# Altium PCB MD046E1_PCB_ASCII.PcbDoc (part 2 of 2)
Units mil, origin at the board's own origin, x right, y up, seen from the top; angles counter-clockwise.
Board outline 4143.7 x 2795.28 mil, 4 copper layers (Top Layer, Signal Layer 1, Signal Layer 2, Bottom Layer), stack 62.8 mil thick; 159 components, 76 nets, 432 pads, 579 vias.
Unrouted connection lines stored in the file: 13.
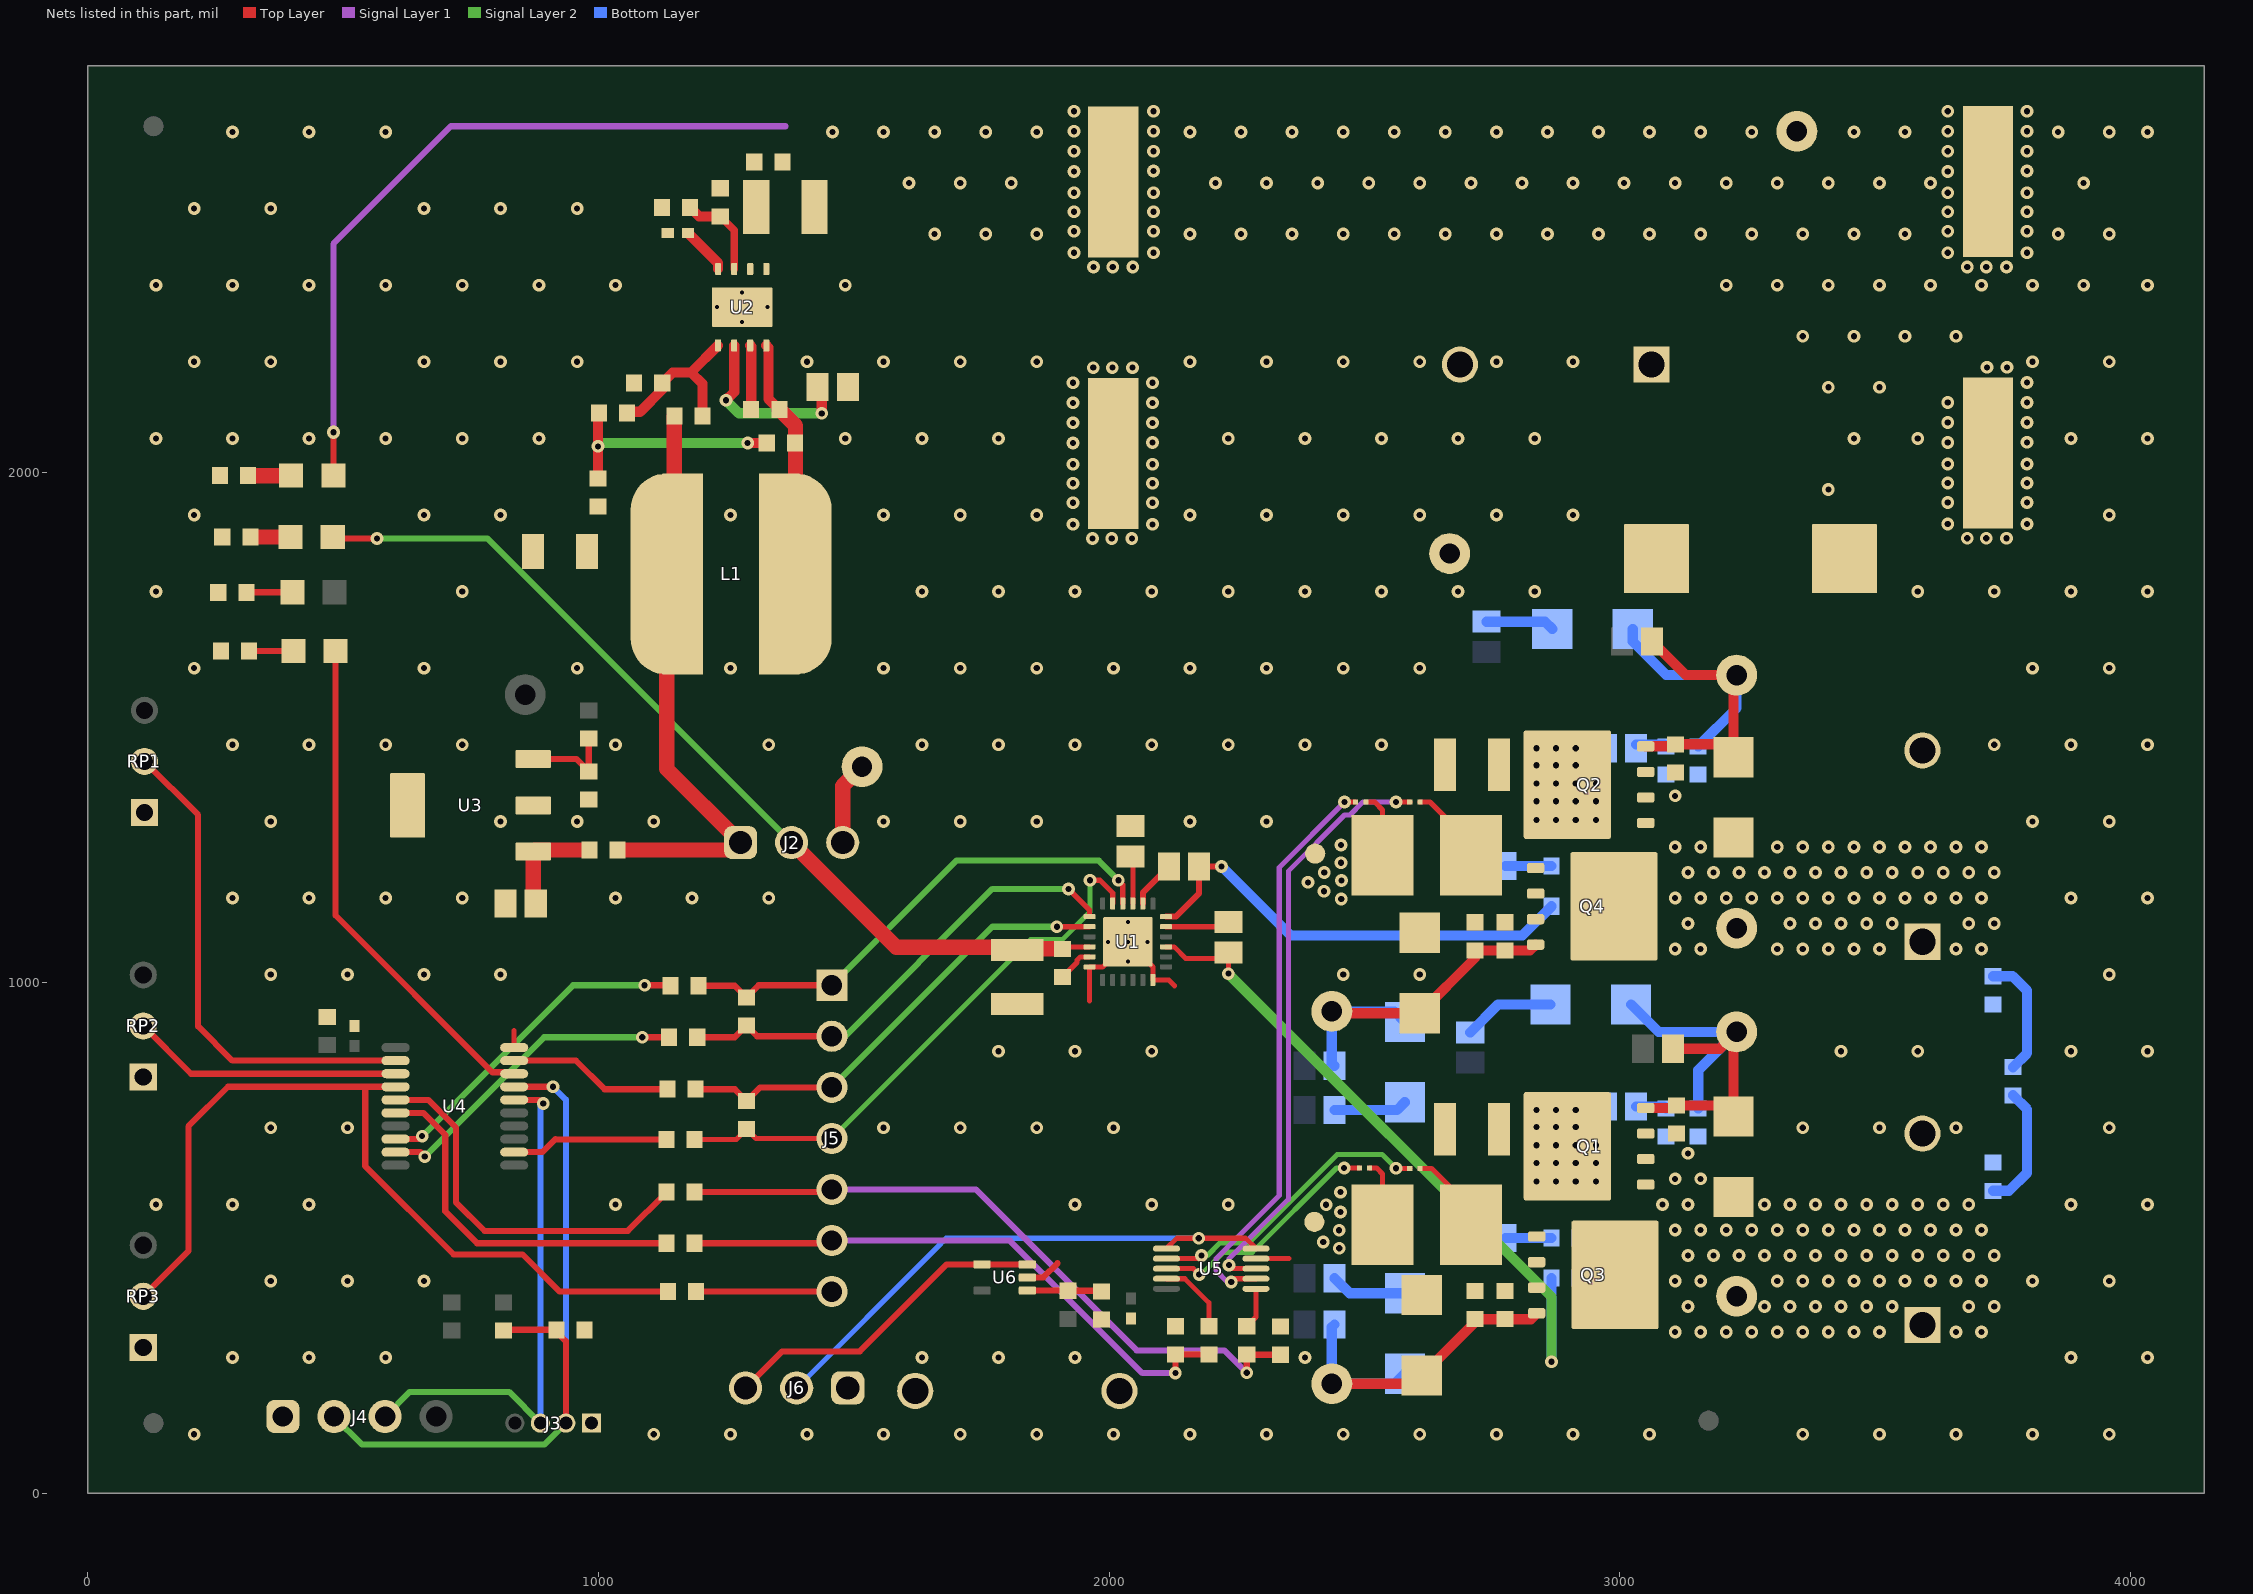
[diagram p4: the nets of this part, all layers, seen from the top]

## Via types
v1: diameter 25, hole 12, Top Layer to Bottom Layer, tented both sides, 566 vias
v2: diameter 19.68, hole 7.87, Top Layer to Bottom Layer, 9 vias
v3: diameter 26, hole 12, Top Layer to Bottom Layer, tented both sides, 4 vias

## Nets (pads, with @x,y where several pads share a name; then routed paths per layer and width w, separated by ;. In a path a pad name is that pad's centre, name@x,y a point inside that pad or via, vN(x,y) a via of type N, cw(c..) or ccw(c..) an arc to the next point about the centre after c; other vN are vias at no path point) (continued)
GND: C2.2 C3.2 C5.2 C6.2 C8.2 C11.2 C12.2 C13.2 C14.2 C15.2 C16.2 C17.2 C26.2 C27.2 C28.2 C29.1 C31.2 C32.2 GND.1 GND.2 J1.2 J3.1 J4.1 J6.1 J7.2 NT3.2 NT4.2 R7.1 R8.1 R9.1 R10.1 R14.1 R20.1 R25.1 R26.1 R30.1 R31.1 R32.1 R33.1 R38.1 RP1.1 RP2.1 RP3.1 TP1.1 TP2.1 U1.6 U1.12 U1.25 U2.1 U2.9 U3.2 U3.4 U4.20 U5.4 U6.2 | length 730.4
  Top Layer w10: U4.20@834.65,873.03 834.65,906.67 ; 1961.42,964.48 U1.6@1961.42,1031.01 1987.01,1031.01 v2(2036.22,1080.23) 2085.44,1031.01 U1.12@2085.44,1005.42 2116.58,1005.42 2127.91,994.09 ; U5.4@2287.21,459.81 2351.92,459.81 ; NT4.2@2502.48,1353.74 2519.68,1353.74 2535.04,1338.39 R26.1@2535.04,1249.36 ; NT3.2@2509.84,637.15 2523.47,637.15 2535.04,625.58 R33.1@2535.04,526.33
  Top Layer w12: U6.2@1839.37,422.94 1870.87,422.94 1898.62,450.69
  other v1: 208,116 1108,116 1258,116 1408,116 1558,116 1708,116 1858,116 2008,116 2158,116 2308,116 2458,116 2608,116 2758,116 2908,116 3058,116 3358,116 3508,116 3658,116 3808,116 3958,116 283,266 433,266 583,266 1633,266 1783,266 1933,266 2383,266 3883,266 4033,266 358,416 508,416 658,416 3808,416 3958,416 2450.32,480.06 2419.06,492.5 2450.1,515.37 2452.5,550.89 2424.69,565.41 133,566 283,566 433,566 1033,566 1933,566 2083,566 2233,566 3883,566 4033,566 2452.66,589.99 358,716 508,716 1558,716 1708,716 1858,716 2008,716 3358,716 3508,716 3658,716 3958,716 1783,866 1933,866 2083,866 3433,866 3583,866 3883,866 4033,866 358,1016 508,1016 658,1016 808,1016 2458,1016 2608,1016 3958,1016 2454.27,1164.17 283,1166 433,1166 583,1166 733,1166 1033,1166 1183,1166 1333,1166 3883,1166 4033,1166 2420.15,1179.2 2388.89,1196.65 2454.72,1200.13 2420.77,1215.76 2453.45,1235.04 2453.45,1269.64 358,1316 808,1316 958,1316 1108,1316 1558,1316 1708,1316 1858,1316 2158,1316 2308,1316 3808,1316 3958,1316 283,1466 433,1466 583,1466 733,1466 1033,1466 1333,1466 1633,1466 1783,1466 1933,1466 2083,1466 2233,1466 2383,1466 2533,1466 3733,1466 3883,1466 4033,1466 208,1616 658,1616 958,1616 1258,1616 1558,1616 1708,1616 1858,1616 2008,1616 2158,1616 2308,1616 2458,1616 2608,1616 3808,1616 3958,1616 133,1766 733,1766 1633,1766 1783,1766 1933,1766 2083,1766 2233,1766 2383,1766 2533,1766 2683,1766 2833,1766 3583,1766 3733,1766 3883,1766 4033,1766 1967.33,1869.84 2004.72,1869.84 2044.09,1869.84 3679.92,1870.42 3717.32,1870.42 3756.69,1870.42 1929.13,1897.64 2084.64,1897.64 3641.73,1898.23 3797.24,1898.23 208,1916 658,1916 808,1916 1258,1916 1558,1916 1708,1916 1858,1916 2158,1916 2308,1916 2458,1916 2608,1916 2758,1916 2908,1916 3958,1916 1929.13,1939.96 2084.64,1939.96 3641.73,1940.55 3797.24,1940.55 1929.13,1978.1 2084.64,1978.1 3641.73,1978.69 3797.24,1978.69 1929.13,2015.28 2084.64,2015.28 3641.73,2015.87 3797.24,2015.87 1929.13,2057.09 2084.64,2057.68 3641.73,2057.68 3797.24,2058.26 133,2066 283,2066 433,2066 583,2066 733,2066 883,2066 1483,2066 1633,2066 1783,2066 2233,2066 2383,2066 2533,2066 2683,2066 2833,2066 3583,2066 3883,2066 4033,2066 1929.13,2096.46 2084.64,2096.46 3641.73,2097.05 3797.24,2097.05 1929.13,2135.58 2084.64,2135.58 3641.73,2136.17 3797.24,2136.17 1929.13,2174.95 2084.64,2174.95 3797.24,2175.54 1968.5,2204.48 2005.9,2204.48 2045.27,2204.48 3718.5,2205.07 3757.87,2205.07 208,2216 358,2216 658,2216 808,2216 958,2216 1408,2216 1558,2216 1708,2216 1858,2216 2158,2216 2308,2216 2458,2216 2608,2216 2758,2216 2908,2216 3808,2216 3958,2216 133,2366 283,2366 433,2366 583,2366 733,2366 883,2366 1033,2366 1483,2366 4033,2366 208,2516 358,2516 658,2516 808,2516 958,2516 283,2666 433,2666 583,2666 4033,2666
  other v2: 2036.22,1041.84 1997.84,1080.23 2074.61,1080.23 2036.22,1118.61 1281.13,2293.7 1231.92,2322.83 1330.35,2322.83 1281.13,2351.97
GVDD: C12.1 GVDD.1 J2.2 R11.2 U1.4 | length 1817.8
  Top Layer w10: R11.2@1908.27,1066.45 1912.21,1070.38 U1.4@1961.42,1070.38
  Top Layer w12: GVDD.1@479.25,1872.86 482.27,1869.84 v3(566.06,1869.84)
  Top Layer w30: J2.2@1377.95,1274.44 1582.99,1069.4 1814.77,1069.4 1817.72,1066.45 R11.2@1908.27,1066.45
  Signal Layer 2 w12: v3(566.06,1869.84) 782.56,1869.84 J2.2@1377.95,1274.44
GVDD_BUCK: C9.1 C11.1 J2.1 L1.2 R6.2 R12.1 | length 1148.1
  Top Layer w30: R12.1@1036.95,1259.84 1263.36,1259.84 J2.1@1277.95,1274.44 1133.41,1418.98 L1.2@1133.41,1800.44 1148.17,1815.2 R6.2@1148.17,2109.49
INHA: J5.1 R39.2 R49.2 U1.22 | length 1008
  Top Layer w10: v1(2017.71,1200.78) 2026.38,1192.12 U1.22@2026.38,1155.03
  Top Layer w12: R39.2@1195.45,994.09 1266.48,994.09 R49.2@1289.37,971.2 1313.39,995.23 J5.1@1456.69,995.23
  Signal Layer 2 w12: J5.1@1456.69,995.23 1700.64,1239.17 1979.32,1239.17 v1(2017.71,1200.78)
INHA_MCU: R39.1 U4.8 | length 663.3
  Top Layer w12: U4.8@602.36,693.9 648.79,693.9 v1(654.47,699.57) ; v1(1090.1,995.23) 1139.2,995.23 R39.1@1140.34,994.09
  Signal Layer 2 w12: v1(654.47,699.57) 950.12,995.23 v1(1090.1,995.23)
INHB: J5.4 R42.2 R50.2 U1.23 | length 1111.4
  Top Layer w10: R42.2@1188.08,693.14 1269.51,693.14 R50.2@1289.84,713.47 1308.09,695.23 J5.4@1456.69,695.23 ; v1(1962.36,1200.79) 1981.83,1200.79 2006.7,1175.92 U1.23@2006.7,1155.03
  Signal Layer 2 w10: J5.4@1456.69,695.23 1845.85,1084.38 1907.76,1084.38 1962.25,1138.88 1962.25,1200.68 v1(1962.36,1200.79)
INHB_MCU: R42.1 U4.12 | length 309.1
  Top Layer w12: U4.12@834.65,668.31 889.88,668.31 915.35,693.78 915.99,693.14 R42.1@1132.96,693.14
INLA: J5.2 R40.2 R49.1 U1.1 | length 936
  Top Layer w10: v1(1920.06,1183.78) 1961.42,1142.43 U1.1@1961.42,1129.44
  Top Layer w12: R40.2@1193.13,893.23 1266.52,893.23 R49.1@1289.37,916.09 1310.23,895.23 J5.2@1456.69,895.23
  Signal Layer 2 w12: J5.2@1456.69,895.23 1482.61,895.23 1771.17,1183.78 v1(1920.06,1183.78)
INLA_MCU: R40.1 U4.9 | length 636.2
  Top Layer w12: U4.9@602.36,668.31 650.59,668.31 v1(659.45,659.45) ; v1(1085.47,893.23) R40.1@1138.01,893.23
  Signal Layer 2 w12: v1(659.45,659.45) 893.23,893.23 v1(1085.47,893.23)
INLB: J5.3 R41.2 R50.1 U1.2 | length 922.2
  Top Layer w10: v1(1897.25,1109.75) U1.2@1961.42,1109.75
  Top Layer w12: R41.2@1190.05,791.57 1266.86,791.57 R50.1@1289.84,768.59 1316.47,795.23 J5.3@1456.69,795.23
  Signal Layer 2 w12: J5.3@1456.69,795.23 1771.22,1109.75 v1(1897.25,1109.75)
INLB_MCU: R41.1 U4.19 | length 323.4
  Top Layer w12: U4.19@834.65,847.44 955.68,847.44 1011.56,791.57 R41.1@1134.93,791.57
ISENA: C27.1 J5.5 R35.2 R43.2 | length 1334.1
  Top Layer w12: R43.2@1188.08,589.99 1451.46,589.99 J5.5@1456.69,595.23 ; v1(2269.1,236.22) R35.2@2269.1,272.29 2269.87,271.51 C27.1@2334.87,271.51
  Signal Layer 1 w12: J5.5@1456.69,595.23 1738.53,595.23 2053.67,280.09 2225.22,280.09 v1(2269.1,236.22)
ISENA_MCU: R43.1 U4.5 | length 754.1
  Top Layer w12: U4.5@602.36,770.67 666.34,770.67 721.05,715.96 721.05,569.55 776.5,514.1 1057.06,514.1 R43.1@1132.96,589.99
ISENB: C28.1 J5.6 R36.2 R44.2 | length 1153.1
  Top Layer w12: R44.2@1188.08,489.99 1451.46,489.99 J5.6@1456.69,495.23 ; v1(2129.3,235.68) C28.1@2129.3,272.29 R36.2@2194.88,272.29
  Signal Layer 1 w12: J5.6@1456.69,495.23 1805.15,495.23 2064.7,235.68 v1(2129.3,235.68)
ISENB_MCU: R44.1 U4.6 | length 723.9
  Top Layer w12: U4.6@602.36,745.08 656.6,745.08 699.61,702.07 699.61,552.52 762.13,489.99 R44.1@1132.96,489.99
MOTA: C19.2 C21.2 C23.1 C29.2 C30.1 D1.2 J8.1 Q2.1 Q2.2 Q2.3 Q4.5 Q4.6 Q4.7 Q4.8 Q4.9@2988.39,1149.56 R18.2 R28.2 SHA1.1 | length 239.7
  Bottom Layer w20: C29.2@3730.31,1012.72 3768.77,1012.72 3797.24,984.25 3797.24,862.2 C30.1@3769.69,834.65
  other v1: 3108,1066 3158,1066 3308,1066 3358,1066 3408,1066 3458,1066 3508,1066 3658,1066 3708,1066 3133,1116 3333,1116 3383,1116 3433,1116 3483,1116 3533,1116 3683,1116 3733,1116 3108,1166 3158,1166 3208,1166 3258,1166 3308,1166 3358,1166 3408,1166 3458,1166 3508,1166 3558,1166 3608,1166 3658,1166 3708,1166 3133,1216 3183,1216 3233,1216 3283,1216 3333,1216 3383,1216 3433,1216 3483,1216 3533,1216 3583,1216 3633,1216 3683,1216 3733,1216 3108,1266 3158,1266 3308,1266 3358,1266 3408,1266 3458,1266 3508,1266 3558,1266 3608,1266 3658,1266 3708,1266 3108,1366
MOTB: C18.2 C20.2 C22.1 C30.2 C31.1 D3.2 J7.1 Q1.1 Q1.2 Q1.3 Q3.5 Q3.6 Q3.7 Q3.8 Q3.9@2990.35,427.9 R21.2 R23.2 SHB1.1 | length 244.6
  Bottom Layer w20: C31.1@3730.31,592.52 3761.81,592.52 3797.24,627.95 3797.24,751.97 C30.2@3769.69,779.53
  other v1: 3108,316 3158,316 3208,316 3258,316 3308,316 3358,316 3408,316 3458,316 3508,316 3658,316 3708,316 3133,366 3283,366 3333,366 3383,366 3433,366 3483,366 3533,366 3683,366 3733,366 3108,416 3158,416 3308,416 3358,416 3408,416 3458,416 3508,416 3558,416 3608,416 3658,416 3708,416 3133,466 3183,466 3233,466 3283,466 3333,466 3383,466 3433,466 3483,466 3533,466 3583,466 3633,466 3683,466 3733,466 3108,516 3158,516 3208,516 3258,516 3308,516 3358,516 3408,516 3458,516 3508,516 3558,516 3608,516 3658,516 3708,516 3083,566 3133,566 3283,566 3333,566 3383,566 3433,566 3483,566 3533,566 3583,566 3633,566 3683,566 3108,616 3158,616 3133,666
Net3.3V_2: 3.3V.2 R14.2 | length 89.9
  Top Layer w12: R14.2@310.33,1764.59 3.3V.2@400.22,1764.59
NetC1_1: C1.1 U1.20 | length 94
  Top Layer w12: U1.20@2065.75,1155.03 2065.75,1176.68 C1.1@2116.93,1227.86
NetC4_1: C4.1 U1.17 | length 125.7
  Top Layer w10: U1.17@2111.03,1109.75 2224.22,1109.75 C4.1@2233.07,1118.61
NetC7_1: C7.1 U2.7 | length 127.1
  Top Layer w20: U2.7@1296.88,2248.03 1298.76,2246.15 C7.1@1298.76,2122.29 C7.1@1299.16,2122.68
NetC7_2: C7.2 L1.1 R5.1 U2.8 | length 471.2
  Top Layer w20: U2.8@1328.38,2248.03 1332.39,2244.02 1332.39,2143.79 C7.2@1353.88,2122.29
  Top Layer w30: C7.2@1353.88,2122.29 1385.38,2090.79 L1.1@1385.38,1800.44
NetC8_1: C8.1 R3.2 R4.2 U2.2
NetC9_2: C9.2 C10.1 R5.2 | length 462.2
  Top Layer w20: C9.2@998.57,1987.45 v1(998.57,2050.44) 998.57,2113.43 C10.1@1000.54,2115.4 ; v1(1291.83,2057.09) R5.2@1329.28,2057.09
  Signal Layer 2 w20: v1(998.57,2050.44) 1005.21,2057.09 v1(1291.83,2057.09)
NetC10_2: C10.2 R6.1 R9.2 U2.5 | length 335.5
  Top Layer w20: C10.2@1055.65,2115.4 1058.6,2118.35 1081.24,2118.35 1124.55,2161.66 R9.2@1124.55,2174.46 1145.22,2195.13 1180.98,2195.13 ; R6.1@1203.29,2109.49 1203.29,2172.82 1180.98,2195.13 ; U2.5@1233.89,2248.03 1180.98,2195.13
NetC13_1: C13.1 R12.2 U3.1 | length 214.9
  Top Layer w30: C13.1@876.76,1155.03 871.95,1159.84 U3.1@871.95,1256.72 875.08,1259.84 R12.2@981.83,1259.84
NetC14_1: C14.1 R13.1 U3.3 | length 182.5
  Top Layer w12: U3.3@871.95,1437.82 956.86,1437.82 C14.1@980.64,1414.05 R13.1@980.64,1478.02
NetC18_1: C18.1 D3.1 D4.2 GHB1.1 Q1.4 R21.1 R22.2 | length 889.6
  Top Layer w20: Q1.4@3050.39,754.72 3105.9,754.72 R21.1@3110.83,759.64 3200.6,759.64 D3.1@3222.05,738.19 GHB1.1@3222.05,897.45 ; R22.2@3103.94,870.82 3195.41,870.82 GHB1.1@3222.05,897.45 ; GHB1.1@3228.35,903.75 GHB1.1@3222.05,897.45
  Bottom Layer w20: D4.2@3021.65,957.6 3075.5,903.75 GHB1.1@3228.35,903.75 3153.15,828.56 C18.1@3153.15,754.15
NetC19_1: C19.1 D1.1 D5.2 GHA1.1 Q2.4 R18.1 R27.2 | length 957.1
  Top Layer w20: Q2.4@3050.39,1462.94 3104.92,1462.94 R18.1@3108.86,1466.88 3196.85,1466.88 D1.1@3222.05,1441.68 GHA1.1@3222.05,1596.27 ; R27.2@3063.02,1668.26 3128.7,1602.57 GHA1.1@3228.35,1602.57
  Bottom Layer w20: D5.2@3024.87,1692.91 3024.87,1668.26 3090.55,1602.57 GHA1.1@3228.35,1602.57 3228.35,1538.01 C19.1@3153.15,1462.81
NetC20_1: C20.1 R17.1 | length 60.2
  Bottom Layer w20: R17.1@3031.5,757.87 3086.43,757.87 C20.1@3090.16,754.15
NetC21_1: C21.1 R2.1 | length 60.2
  Bottom Layer w20: R2.1@3031.5,1466.54 3086.43,1466.54 C21.1@3090.16,1462.81
NetC22_2: C22.2 R31.2 | length 90.6
  Bottom Layer w20: R31.2@2775.59,500.21 C22.2@2866.14,500.21
NetC23_2: C23.2 R25.2 | length 90.6
  Bottom Layer w20: R25.2@2775.59,1228.56 C23.2@2866.14,1228.56
NetC24_1: C24.1 D7.1 D8.2 GLB1.1 Q3.4 R29.1 R46.2 | length 731.1
  Top Layer w20: GLB1.1@2435.74,214.78 2595.54,214.78 D7.1@2611.81,231.05 2716.14,335.38 C24.1@2716.14,341.29 R29.1@2775.2,341.29 2825.2,341.29 Q3.4@2836.81,352.9
  Bottom Layer w20: R46.2@2440.94,330.82 2435.74,325.61 GLB1.1@2435.74,214.78 2559.06,214.78 D8.2@2578.74,234.46
NetC24_2: C24.2 D7.2 NT1.2 Q3.1 Q3.2 Q3.3 R29.2 R33.2 | length 164.9
  Top Layer w10: NT1.2@2608.43,636.66 2630.92,636.66 2708.27,559.31 R33.2@2708.27,526.33
NetC25_1: C25.1 D2.1 D6.2 GLA1.1 Q4.4 R24.1 R47.2 | length 725
  Top Layer w20: GLA1.1@2435.74,943.82 2439.3,940.27 D2.1@2608,940.27 2716.14,1048.41 C25.1@2716.14,1063.34 R24.1@2775.2,1063.34 2823.62,1063.34 Q4.4@2834.84,1074.56
  Bottom Layer w20: R47.2@2440.94,837.35 2435.74,842.55 GLA1.1@2435.74,943.82 2558.36,943.82 D6.2@2578.74,923.44
NetC25_2: C25.2 D2.2 NT2.2 Q4.1 Q4.2 Q4.3 R24.2 R26.2 | length 157.2
  Top Layer w10: NT2.2@2608.43,1353.74 2627.95,1353.74 2708.27,1273.43 R26.2@2708.27,1249.36
NetC32_1: C32.1 U2.6 | length 367.7
  Top Layer w20: v1(1249.16,2140.62) 1265.39,2156.85 U2.6@1265.39,2248.03 ; C32.1@1428.96,2166.88 1437.01,2158.82 v1(1437.01,2115.04)
  Signal Layer 2 w20: v1(1249.16,2140.62) 1274.73,2115.04 v1(1437.01,2115.04)
NetD4_1: D4.1 R1.2 | length 180.3
  Bottom Layer w20: R1.2@2706.69,902.56 2761.74,957.6 D4.1@2864.17,957.6
NetD5_1: D5.1 R19.2 | length 134.3
  Bottom Layer w20: R19.2@2738.94,1707.09 2853.21,1707.09 D5.1@2867.39,1692.91
NetD6_1: D6.1 R34.2 | length 144.1
  Bottom Layer w20: R34.2@2440.94,750.78 2563.56,750.78 D6.1@2578.74,765.96
NetD8_1: D8.1 R45.2 | length 150
  Bottom Layer w20: R45.2@2440.94,421.47 2470.47,391.94 D8.1@2578.74,391.94
NetF1_2: F1.2 J1.1
NetGVDD_2: GVDD.2 R32.2 | length 78.4
  Top Layer w30: R32.2@318.12,1872.86 GVDD.2@396.57,1872.86
NetGVDD_EXT_1: GVDD_EXT.1 J2.3 | length 164.3
  Top Layer w30: J2.3@1477.95,1274.44 1477.95,1385.29 GVDD_EXT.1@1515.75,1423.09
NetJ5_7: J5.7 R48.2 | length 266
  Top Layer w12: R48.2@1190.88,395.71 1456.21,395.71 J5.7@1456.69,395.23
NetJ6_3: J6.3 U6.3 U6.4 | length 651.7
  Top Layer w12: J6.3@1287.8,206.69 1359.1,277.99 1511.26,277.99 1681.79,448.53 U6.4@1750.79,448.53 U6.3@1839.37,448.53
NetPVDD_2: PVDD.2 R30.2 | length 84.3
  Top Layer w30: R30.2@313.66,1993.09 PVDD.2@397.94,1993.09
NetR4_1: R4.1 R7.2 U2.3 | length 180.6
  Top Layer w15: R4.1@1238.13,2500.76 1265.39,2473.51 U2.3@1265.39,2397.64
  Top Layer w20: R7.2@1179.13,2518.14 1196.51,2500.76 R4.1@1238.13,2500.76
NetR8_2: R8.2 U2.4 | length 95.2
  Top Layer w20: R8.2@1174.75,2468.34 1233.89,2409.2 U2.4@1233.89,2397.64
NetR10_2: R10.2 U1.21 | length 94.3
  Top Layer w10: R10.2@2041.74,1247.55 2046.07,1243.22 U1.21@2046.07,1155.03
NetR11_1: R11.1 U1.5 | length 72.1
  Top Layer w10: R11.1@1908.27,1011.33 1936.74,1039.79 1936.74,1044.22 1943.21,1050.7 U1.5@1961.42,1050.7
NetR20_2: R20.2 STATUS.2 | length 87.1
  Top Layer w12: R20.2@315.32,1649.68 STATUS.2@402.41,1649.68
NetR37_1: R37.1 R38.2 U6.1 | length 145.8
  Top Layer w12: U6.1@1839.37,397.35 1918.78,397.35 R37.1@1919.29,396.83 1983.31,396.83 R38.2@1984.45,395.69
PVDD: C2.1 C3.1 C5.1 C6.1 F1.1 J8.2 PVDD.1 Q1.5 Q1.6 Q1.7 Q1.8 Q1.9@2896.85,679.72 Q2.5 Q2.6 Q2.7 Q2.8 Q2.9@2896.85,1387.94 R2.2 R3.1 R17.2 | length 1434.2
  Top Layer w12: PVDD.1@480.62,1993.09 480.62,2061.7 v3(480.62,2078.06)
  Signal Layer 1 w12: v3(480.62,2078.06) 480.62,2446.91 710.88,2677.17 1365.6,2677.17
  other v1: 2836.81,610.84 2874.55,610.84 2913.39,610.84 2952.76,610.84 2836.81,647.17 2874.55,647.17 2913.39,647.17 2952.76,647.17 2836.81,681.87 2874.55,681.87 2913.39,681.87 2952.76,681.87 2836.81,717.72 2874.55,717.72 2913.39,717.72 2836.81,751.11 2874.55,751.11 2913.39,751.11 2836.81,1319.07 2874.55,1319.07 2913.39,1319.07 2952.76,1319.07 2836.81,1355.39 2874.55,1355.39 2913.39,1355.39 2952.76,1355.39 2836.81,1390.09 2874.55,1390.09 2913.39,1390.09 2952.76,1390.09 2836.81,1425.94 2874.55,1425.94 2913.39,1425.94 2836.81,1459.33 2874.55,1459.33 2913.39,1459.33 3408,1966 3458,2066 3408,2166 3508,2166 3358,2266 3458,2266 3558,2266 3658,2266 3208,2366 3308,2366 3408,2366 3508,2366 3608,2366 3708,2366 3808,2366 3908,2366 1969.3,2401.57 2006.7,2401.57 2046.07,2401.57 3679.92,2401.57 3717.32,2401.57 3756.69,2401.57 1931.11,2429.38 2086.61,2429.38 3641.73,2429.38 3797.24,2429.38 1658,2466 1758,2466 1858,2466 2158,2466 2258,2466 2358,2466 2458,2466 2558,2466 2658,2466 2758,2466 2858,2466 2958,2466 3058,2466 3158,2466 3258,2466 3358,2466 3458,2466 3558,2466 3858,2466 3958,2466 1931.11,2471.7 2086.61,2471.7 3641.73,2471.7 3797.24,2471.7 1931.11,2509.84 2086.61,2509.84 3641.73,2509.84 3797.24,2509.84 1931.11,2547.02 2086.61,2547.02 3641.73,2547.02 3797.24,2547.02 1608,2566 1708,2566 1808,2566 2208,2566 2308,2566 2408,2566 2508,2566 2608,2566 2708,2566 2808,2566 2908,2566 3008,2566 3108,2566 3208,2566 3308,2566 3408,2566 3508,2566 3608,2566 3908,2566 1931.11,2588.83 2086.61,2589.41 3641.73,2588.83 3797.24,2589.41 1931.11,2628.2 2086.61,2628.2 3641.73,2628.2 3797.24,2628.2 1458,2666 1558,2666 1658,2666 1758,2666 1858,2666 2158,2666 2258,2666 2358,2666 2458,2666 2558,2666 2658,2666 2758,2666 2858,2666 2958,2666 3058,2666 3158,2666 3258,2666 3458,2666 3558,2666 3858,2666 3958,2666 1931.11,2667.32 2086.61,2667.32 3641.73,2667.32 3797.24,2667.32 1931.11,2706.69 2086.61,2706.69 3641.73,2706.69 3797.24,2706.69
REF: J6.2 U5.5 U5.6 | length 1100.7
  Top Layer w10: U5.6@2112.01,479.49 2132.19,499.68 v1(2175.2,499.68) 2267.03,499.68 U5.5@2287.21,479.49
  Bottom Layer w10: J6.2@1387.8,206.69 1660.6,479.49 1680.78,499.68 v1(2175.2,499.68)
SBWTCK: J3.3 J4.3 U4.16 | length 1037.2
  Top Layer w12: U4.16@834.65,770.67 884.36,770.67 v1(891.52,763.5)
  Signal Layer 2 w12: J4.3@581.75,150.63 629.92,198.8 824.82,198.8 J3.3@885.83,137.8
  Bottom Layer w12: J3.3@885.83,137.8 885.83,757.81 v1(891.52,763.5)
SBWTDIO: C17.1 J3.2 J4.2 R15.1 U4.17 | length 1527.5
  Top Layer w12: R15.1@816.93,320.42 913.39,320.42 935.83,297.98 J3.2@935.83,137.8 ; U4.17@834.65,796.26 v1(910.43,796.26)
  Signal Layer 2 w12: J4.2@481.75,150.63 536.8,95.58 893.61,95.58 J3.2@935.83,137.8
  Bottom Layer w12: v1(910.43,796.26) 935.83,770.87 J3.2@935.83,137.8
SHA: C1.2 R28.1 U1.18 | length 906.6
  Top Layer w12: U1.18@2111.03,1129.44 2130.4,1129.44 2175.99,1175.03 C1.2@2175.99,1227.86 v1(2219.77,1227.86)
  Bottom Layer w20: v1(2219.77,1227.86) 2355.11,1092.52 2808.84,1092.52 R28.1@2866.14,1149.82
SHB: C4.2 R23.1 U1.15 | length 1363.6
  Top Layer w10: U1.15@2111.03,1070.38 2126.98,1070.38 2149.62,1047.74 2221.26,1047.74 C4.2@2233.07,1059.56 v1(2233.07,1017.82)
  Signal Layer 2 w20: v1(2233.07,1017.82) 2866.14,384.76 v1(2866.14,257.96)
  Bottom Layer w20: v1(2866.14,257.96) R23.1@2866.14,421.47
SNA: NT4.1 U5.2 | length 1135.6
  Top Layer w10: v1(2238.68,414.23) 2244.89,420.44 U5.2@2287.21,420.44 ; v1@2458.49,1353.74 v1(2460.63,1353.74) NT4.1@2482.48,1353.74
  Signal Layer 1 w10: v1(2238.68,414.23) 2231.12,414.23 2208.88,436.48 2208.88,459.55 2332.68,583.35 2332.68,1225.79 v1(2460.63,1353.74)
SNB: NT3.1 U5.8 | length 469.1
  Top Layer w10: U5.8@2112.01,440.12 2164.37,440.12 v1(2175.99,428.51) ; v1(2459.84,637.15) NT3.1@2489.84,637.15
  Signal Layer 2 w10: v1(2175.99,428.51) 2179.89,428.51 2223.74,472.36 2280.05,472.36 2444.84,637.15 v1(2459.84,637.15)
SOA: R35.1 U5.1 | length 80.8
  Top Layer w10: R35.1@2269.1,327.41 2287.21,345.52 U5.1@2287.21,400.75
SOB: R36.1 U5.9 | length 148.4
  Top Layer w10: U5.9@2112.01,420.44 2147.94,420.44 2194.88,373.5 R36.1@2194.88,327.41
SPA: NT2.1 U5.3 | length 1169.3
  Top Layer w10: v1(2234.25,446.99) 2241.12,440.12 U5.3@2287.21,440.12 ; v1(2561.53,1353.74) NT2.1@2588.43,1353.74
  Signal Layer 1 w10: v1(2234.25,446.99) 2234.25,459.65 2350.55,575.95 2350.55,1218.38 2460.53,1328.37 2471.14,1328.37 2496.51,1353.74 v1(2561.53,1353.74)
SPB: NT1.1 U5.7 | length 572.2
  Top Layer w10: U5.7@2112.01,459.81 2174.32,459.81 v1(2180.52,466) ; v1(2561.53,636.66) NT1.1@2588.43,636.66
  Signal Layer 2 w10: v1(2180.52,466) 2192.1,466 2216.34,490.24 2272.65,490.24 2446.31,663.9 2534.28,663.9 v1(2561.53,636.66)
SPD_REF_1: RP1.2 U4.2 | length 976.8
  Top Layer w12: RP1.2@110.65,1433.49 215.53,1328.61 215.53,914.85 282.94,847.44 U4.2@602.36,847.44
SPD_REF_2: RP2.2 U4.3 | length 532.8
  Top Layer w12: RP2.2@108.27,915.35 201.77,821.85 U4.3@602.36,821.85
SPD_REF_3: R48.1 RP3.2 U4.4 | length 1656.7
  Top Layer w12: RP3.2@108.3,386.04 196.85,474.59 196.85,718.86 274.25,796.26 543.08,796.26 ; U4.4@602.36,796.26 543.08,796.26 ; R48.1@1135.76,395.71 923.19,395.71 851.01,467.89 716.1,467.89 543.08,640.91 543.08,796.26
STATUS: STATUS.1 U4.18 | length 995.9
  Top Layer w12: STATUS.1@485.08,1649.68 485.08,1131.7 792.07,824.71 831.79,824.71 U4.18@834.65,821.85
pads on no net: FID1.1 FID2.1 FID3.1 FID4.1 FID5.1 FID6.1 H1.0 H2.0 H3.0 H4.0 LBL1.0 Q1.9@2869.88,627.36 Q1.9@2869.88,679.72 Q1.9@2869.88,732.08 Q1.9@2909.84,679.72 Q1.9@2915.16,627.36 Q1.9@2915.16,679.72 Q1.9@2915.16,732.08 Q1.9@2960.43,627.36 Q1.9@2960.43,679.72 Q1.9@2960.43,732.08 Q1.9@2972.05,586.31 Q1.9@2972.05,773.12 Q2.9@2869.88,1335.58 Q2.9@2869.88,1387.94 Q2.9@2869.88,1440.3 Q2.9@2909.84,1387.94 Q2.9@2915.16,1335.58 Q2.9@2915.16,1387.94 Q2.9@2915.16,1440.3 Q2.9@2960.43,1335.58 Q2.9@2960.43,1387.94 Q2.9@2960.43,1440.3 Q2.9@2972.05,1294.54 Q2.9@2972.05,1481.35 Q3.9@2915.16,334.5 Q3.9@2915.16,521.31 Q3.9@2926.77,375.54 Q3.9@2926.77,427.9 Q3.9@2926.77,480.26 Q3.9@2972.05,375.54 Q3.9@2972.05,427.9 Q3.9@2972.05,480.26 Q3.9@2977.36,427.9 Q3.9@3017.32,375.54 Q3.9@3017.32,427.9 Q3.9@3017.32,480.26 Q4.9@2913.19,1056.15 Q4.9@2913.19,1242.96 Q4.9@2924.8,1097.19 Q4.9@2924.8,1149.56 Q4.9@2924.8,1201.92 Q4.9@2970.08,1097.19 Q4.9@2970.08,1149.56 Q4.9@2970.08,1201.92 Q4.9@2975.39,1149.56 Q4.9@3015.35,1097.19 Q4.9@3015.35,1149.56 Q4.9@3015.35,1201.92 SH-J1.0 SH-J2.0 U1.3 U1.7 U1.8 U1.9 U1.13 U1.14 U1.24 U4.7 U4.10 U4.11 U4.13 U4.14 U4.15
copper on no net: | length 3.5
  Top Layer w10: 1736.03,915.35 1738.53,917.86

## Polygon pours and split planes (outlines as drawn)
PVDD on Top Layer "TOP_LAYER_PVDD_P101" (solid, remove dead copper, pour order 101): 2742.22,763.5 2851.69,763.5 2851.69,660.16 2742.22,660.16
PVDD on Top Layer "TOP_LAYER_PVDD_P099" (solid, remove dead copper, pour order 99): 2741.26,1478.02 2851.69,1478.33 2851.69,1375.79 2741.26,1375.79
MOTB on Top Layer "TOP_LAYER_MOTB_P090" (solid, remove dead copper, pour order 90): 2903.64,537.49 2903.64,265.8 3750,265.7 3750,604.72 3198.04,604.72 3153.15,649.61 3153.15,699.8 3134.45,718.5 3032.42,718.5 3027.25,713.34 3027.25,567.27 2997.47,537.49
MOTA on Top Layer "TOP_LAYER_MOTA_P082" (solid, remove dead copper, pour order 82): 2903.64,1039.42 3062.99,1039.42 3062.99,1004.44 3750,1004.44 3750,1326.61 3182.68,1326.61 3139.76,1369.53 3139.76,1429.93 3134.45,1435.25 3026.18,1435.04 3018.31,1427.17 3018.31,1280.89 2997.47,1260.05 2901.48,1260.05
NetC24_2 on Top Layer "TOP_LAYER_NETC24_2_P080" (solid, remove dead copper, pour order 80): 2570.62,349.43 2651.57,349.43 2651.57,356.76 2674.5,379.69 2852.77,379.69 2860.06,386.98 2860.06,515.37 2849.62,525.81 2809.14,525.81 2789.37,545.71 2789.37,590.77 2775.42,604.72 2645.79,604.72 2645.79,449.23 2626.43,429.87 2570.62,429.87
NetC25_2 on Top Layer "TOP_LAYER_NETC25_2_P078" (solid, remove dead copper, pour order 78): 2566.69,1058.57 2647.64,1058.57 2647.64,1080.95 2670.56,1103.88 2848.83,1103.88 2856.12,1111.17 2856.12,1239.56 2845.68,1250 2805.21,1250 2785.43,1269.9 2785.43,1314.96 2771.65,1328.74 2647.64,1328.74 2647.64,1179.2 2613.81,1145.38 2566.69,1145.38
GND on Top Layer "TOP_LAYER_GND_P103" (solid, pour order 103): 0,0 4143.7,0 4143.7,2795.28 0,2795.28
PVDD on Top Layer "TOP_LAYER_PVDD_P035" (solid, remove dead copper, pour order 35): 1574.8,2384.03 1596.43,2362.41 3149.61,2362.2 3366.14,2145.67 3366.14,1761.81 3503.94,1761.81 3503.94,2015.41 3697.34,2293.31 3953.03,2293.31 3986.22,2326.5 3986.22,2726.38 3917.32,2795.28 1409.98,2795.28 1344.83,2730.13 1344.83,2588.83 1545.28,2588.83 1574.8,2559.06
GVDD_BUCK on Top Layer "TOP_LAYER_GVDD_BUCK_P016" (solid, remove dead copper, pour order 16): 1194.43,1948.82 1194.43,1771.65 955.32,1771.65 955.32,1948.82
NetC8_1 on Top Layer "TOP_LAYER_NETC8_1_P000" (solid, remove dead copper, pour order 0): 1319.83,2626.23 1319.83,2572.09 1335.03,2572.09 1335.03,2465.79 1312.54,2465.79 1312.54,2379.03 1289.37,2379.03 1289.37,2539.37 1217.46,2539.37 1217.46,2626.07
NetF1_2 on Top Layer "TOP_LAYER_NETF1_2_P010" (solid, remove dead copper, pour order 10): 3134.45,1764.59 3134.45,2263.78 2982.28,2263.78 2982.28,1899.61 2982.28,1764.59
no net on Signal Layer 1 "SIGNAL_LAYER_1_NONET_P111" (solid, remove dead copper, pour order 111): 3503.94,1685.07
MOTB on Signal Layer 1 "SIGNAL_LAYER_1_MOTB_P092" (solid, remove dead copper, pour order 92): 3064.78,600.39 3750,600.39 3750,265.75 3064.78,265.75
MOTA on Signal Layer 1 "SIGNAL_LAYER_1_MOTA_P084" (solid, remove dead copper, pour order 84): 3064.78,1328.74 3750,1328.74 3750,1004.44 3064.78,1004.44
PVDD on Signal Layer 1 "SIGNAL_LAYER_1_PVDD_P053" (solid, remove dead copper, pour order 53): 1574.8,2384.03 1596.43,2362.41 3149.61,2362.2 3149.61,1948.82 2765.75,1574.8 2765.75,541.34 3031.5,541.34 3031.5,1535.43 3257.87,1761.81 3366.14,1761.81 3366.14,1368.11 3681.1,1368.11 3679.92,1369.29 3679.92,1594.49 3503.94,1770.48 3503.94,2015.41 3697.34,2293.31 3953.03,2293.31 3986.22,2326.5 3986.22,2726.38 3937.01,2775.59 1390.3,2775.59 1344.83,2730.13 1344.83,2588.83 1545.28,2588.83 1574.8,2559.06
GND on Signal Layer 1 "SIGNAL_LAYER_1_GND_P107" (solid, pour order 107): 0,0 4143.7,0 4143.7,2795.28 0,2795.28
MOTB on Signal Layer 2 "SIGNAL_LAYER_2_MOTB_P094" (solid, remove dead copper, pour order 94): 3064.78,265.75 3750,265.75 3750,600.39 3064.78,600.39
MOTA on Signal Layer 2 "SIGNAL_LAYER_2_MOTA_P086" (solid, remove dead copper, pour order 86): 3064.78,1328.74 3750,1328.74 3750,1004.44 3064.78,1004.44
PVDD on Signal Layer 2 "SIGNAL_LAYER_2_PVDD_P054" (solid, remove dead copper, pour order 54): 3697.34,2293.31 3953.03,2293.31 3986.22,2326.5 3986.22,2726.38 3937.01,2775.59 1390.3,2775.59 1344.83,2730.13 1344.83,2588.83 1545.28,2588.83 1574.8,2559.06 1574.8,2384.03 1596.43,2362.41 3149.61,2362.2 3149.61,1948.82 2765.75,1574.8 2765.75,541.34 3031.5,541.34 3031.5,1535.43 3257.87,1761.81 3366.14,1761.81 3366.14,1368.11 3681.1,1368.11 3679.92,1369.29 3679.92,1594.49 3503.94,1770.48 3503.94,2015.41
GND on Signal Layer 2 "SIGNAL_LAYER_2_GND_P105" (solid, pour order 105): 0,0 4143.7,0 4143.7,2795.28 0,2795.28
MOTB on Bottom Layer "BOTTOM_LAYER_MOTB_P095" (solid, remove dead copper, pour order 95): 3750,265.75 3750,598.27 3368.27,598.27 3316.93,649.61 3257.38,709.15 3026.09,709.15 3019.96,703.03 3019.96,554.21 2997.47,531.71 2903.54,531.71 2903.54,265.75
MOTA on Bottom Layer "BOTTOM_LAYER_MOTA_P088" (solid, remove dead copper, pour order 88): 3750,1003.94 3750,1338.58 3356.3,1338.58 3316.93,1377.95 3271.79,1423.09 3025.2,1423.09 3019.96,1417.86 3019.96,1282.55 2997.47,1260.05 2903.54,1260.05 2903.54,1003.94
PVDD on Bottom Layer "BOTTOM_LAYER_PVDD_P064" (solid, remove dead copper, pour order 64): 2814.96,580.71 2982.28,580.71 2982.28,777.56 2814.96,777.56
PVDD on Bottom Layer "BOTTOM_LAYER_PVDD_P055" (solid, remove dead copper, pour order 55): 2814.96,1299.21 2982.28,1299.21 2982.28,1496.06 2814.96,1496.06
GND on Bottom Layer "BOTTOM_LAYER_GND_P109" (solid, pour order 109): 0,0 4143.7,0 4143.7,2795.28 0,2795.28
PVDD on Bottom Layer "Signal Layer 2-PVDD" (solid, remove dead copper, pour order 49): 1574.8,2384.03 1596.43,2362.41 3149.61,2362.2 3366.14,2145.67 3366.14,1761.81 3503.94,1761.81 3503.94,2015.41 3697.34,2293.31 3953.03,2293.31 3986.22,2326.5 3986.22,2726.38 3917.32,2795.28 1409.98,2795.28 1344.83,2730.13 1344.83,2588.83 1545.28,2588.83 1574.8,2559.06

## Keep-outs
Keep-Out Layer:
  text ".Layer_Name" at 577,-858.49 h60

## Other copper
Top Layer:
  text ".Layer_Name" at 577,-858.49 h60
Bottom Layer:
  text ".Layer_Name" at 577,-858.49 h60

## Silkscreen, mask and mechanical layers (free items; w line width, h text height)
Top Overlay:
  rectangle: 2128.18,650.59 2284.92,711.53
  lines w10: 1151.57,1142.43 1220.47,1211.84 ; 1215.57,300.63 1247.93,268.27 ; 1401.18,1386.65 1448.59,1339.25 ; 1547.16,168.76 1591.27,124.65 ; 1735.6,880.73 1741.36,1345.6 2287.21,1345.6 2284.53,880.73 1735.6,880.73
  text "GND" at 2598.43,2696.85 h40
  text "PVDD" at 2988.39,2696.85 h40
  text "IN1_PWM" at 241.43,1558.98 h40 r270
  text "PVDD" at 4104.33,1368.11 h40 r90
  text "GVDD_SEL" at 1263.16,1165.51 h40
  text "GVDD_INT" at 1017.27,1078.26 h40
  text "IN2_PWM" at 244.35,1064.19 h40 r270
  text "MOTA" at 4104.33,989.63 h40 r90
  text "INHA" at 1537.8,972.12 h40
  text "INLA" at 1529.79,873.69 h40
  text "DRV8770" at 1845.85,805.24 h50
  text "INLB" at 1528.94,764.49 h40
  text "INHB" at 1528.94,667.81 h40
  text "'.PRJ_Number'.PCB_Rev-" at 1741.36,657.45 h50
  text "GND" at 4104.33,619.49 h40 r90
  text "ISENA" at 1528.94,568.57 h40
  text "ISENB" at 1528.94,458.76 h40
  text "REF" at 237.64,453.59 h40 r270
  text "REF" at 1528.94,371.47 h40
  text "AREF" at 1057.06,280.09 h40
  text "MOTB" at 4104.33,230.96 h40 r90
  text "CSA_REF" at 1255.46,90.5 h40
  text "GND" at 1608,78.74 h40
  text ".Layer_Name" at 577,-858.49 h60
Bottom Overlay:
  text ".Layer_Name" at 577,-858.49 h60
Top Paste:
  text ".Layer_Name" at 577,-858.49 h60
Bottom Paste:
  text ".Layer_Name" at 577,-858.49 h60
Top Solder:
  text ".Layer_Name" at 577,-858.49 h60
  text ".Layer_Name" at 577,-858.49 h60
Bottom Solder:
  text ".Layer_Name" at 577,-858.49 h60
Drill Guide:
  text ".Layer_Name" at 577,-858.49 h60
M1 Board Outline:
  the board outline again, w10
  text ".Layer_Name" at 577,-858.49 h60
M2 Board Dimensions:
  rectangle: 0,-275 125,-150
  rectangle: 125,-400 500,-275
  lines w7: 0,-275 1000,-275 ; 125,-400 125,-150 ; 250,-400 250,-150 ; 500,-400 500,-150 ; 750,-400 750,-150 ; 0,-400 1000,-400 1000,-150 0,-150 0,-400
  text ".Layer_Name" at 577,-858.49 h60
M3 3D STEP Top:
  text ".Layer_Name" at 577,-858.49 h60
M4 3D STEP Bottom:
  text ".Layer_Name" at 577,-858.49 h60
M5 Assembly Top:
  lines w10: -292,-930.17 6308,-930.17 ; -292,-726.83 6310,-726.83 ; -292,-523.5 -292,-1133.5 3713,-1133.5 6310,-1133.5 6310,-523.5 -291.5,-523.5 -291.5,-1133.5 1284,-1133.5 ; 2173,-1133.5 2173,-523.5 ; 3440,-726.83 3440,-523.5 ; 4280,-726.83 4280,-523.5 ; 4902,-1140 4902,-937.17
  text "COMPONENTS MARKED 'DNP' SHOULD NOT BE POPULATED." at 1153.5,-318.5 h60
  text "ASSEMBLY VARIANT:" at 1153,-434 h60
  text ".VariantName" at 2189,-434 h60
  text "PCB VIEWED FROM TOP SIDE" at -228.5,-655.67 h60
  text "BOARD #:" at 2248,-655.67 h60
  text ".PRJ_Number" at 2793.5,-655.67 h60
  text "REV:" at 3638,-655.67 h60
  text ".PCB_Rev" at 3929.5,-655.67 h60
  text "SVN REV:" at 4476,-655.67 h60
  text ".VersionControl_RevNumber" at 4982,-655.67 h60
  text "TID #:" at 2248,-859 h60
  text ".TID" at 2793.5,-859 h60
  text "PLOT NAME =" at -228.5,-1064.34 h60
  text ".plot_File_Name" at 577,-1064.34 h60
  text "GENERATED    :" at 2250,-1064.34 h60
  text ".Print_Date" at 3119.5,-1064.34 h60
  text ".Print_Time" at 3848.5,-1064.34 h60
  text "TEXAS INSTRUMENTS" at 5113,-1064.34 h60
M6 Assembly Bottom:
  lines w10: -292.5,-727.33 6309.5,-727.33 ; -290.5,-930.67 6309.5,-930.67 ; 1115.5,-1140.5 1115.5,-937.67 ; 1737.5,-727.33 1737.5,-524 ; 2577.5,-727.33 2577.5,-524 ; 3844.5,-1134 3844.5,-524 ; 4733.5,-1134 6309,-1134 6309,-524 -292.5,-524 -292.5,-1134 2304.5,-1134 6309.5,-1134 6309.5,-524
  text "COMPONENTS MARKED 'DNP' SHOULD NOT BE POPULATED." at 6102,-318 h60
  text ".VariantName" at 5058,-434 h60
  text "ASSEMBLY VARIANT:" at 6097,-434 h60
  text ".VersionControl_RevNumber" at 1035.5,-656.17 h60
  text "SVN REV:" at 1541.5,-656.17 h60
  text ".PCB_Rev" at 2088,-656.17 h60
  text "REV:" at 2379.5,-656.17 h60
  text ".PRJ_Number" at 3224,-656.17 h60
  text "BOARD #:" at 3769.5,-656.17 h60
  text "PCB VIEWED FROM BOTTOM SIDE" at 6246,-656.17 h60
  text ".TID" at 3224,-859.5 h60
  text "TID #:" at 3769.5,-859.5 h60
  text "TEXAS INSTRUMENTS" at 904.5,-1064.84 h60
  text ".Print_Time" at 2169,-1064.84 h60
  text ".Print_Date" at 2898,-1064.84 h60
  text "GENERATED    :" at 3767.5,-1064.84 h60
  text ".plot_File_Name" at 5440.5,-1064.84 h60
  text "PLOT NAME =" at 6246,-1064.84 h60
M9 Title Sheet:
  lines w10: -491.5,1041.5 -291.5,1041.5 ; -491.5,3416.5 -291.5,3416.5 ; -491.5,5791.5 -291.5,5791.5 ; 2008.5,-1333.5 2008.5,-1133.5 ; 2008.5,7966.5 2008.5,8166.5 ; 4508.5,-1333.5 4508.5,-1133.5 ; 4508.5,7966.5 4508.5,8166.5 ; 6321,-1133.5 6321,-523.5 11303.5,-523.5 ; 7008.5,-1333.5 7008.5,-1133.5 ; 7008.5,7966.5 7008.5,8166.5 ; 9508.5,-1333.5 9508.5,-1133.5 ; 9508.5,7966.5 9508.5,8166.5 ; 11303.5,-1133.5 11303.5,-523.5 ; 11303.5,-823.5 14303.5,-823.5 ; 11303.5,-223.5 14303.5,-223.5 ; 11304.5,370.5 14304.5,370.5 ; 12008.5,-1333.5 12008.5,-1133.5 ; 12008.5,7966.5 12008.5,8166.5 ; 12808.5,-1123.5 12808.5,-523.5 ; 14303.5,-523.5 11303.5,-523.5 ; 14303.5,76.5 11303.5,76.5 ; 14308.5,66.5 14308.5,-1133.5 ; 14308.5,871 11304.5,871 11303.5,871 11303.5,370.5 11303.5,76.5 ; 14308.5,1041.5 14508.5,1041.5 ; 14308.5,3416.5 14508.5,3416.5 ; 14308.5,5791.5 14508.5,5791.5 ; 11303.5,-523.5 11303.5,76.5 ; 14308.5,-1133.5 14308.5,7966.5 -291.5,7966.5 -291.5,-1133.5 14308.5,-1133.5 ; -491.5,-1333.5 -491.5,8166.5 14508.5,8166.5 14508.5,-1333.5 -491.5,-1333.5
  text "1" at 739.84,8036.5 h70
  text "2" at 3235.5,8036.5 h70
  text "3" at 5724.84,8036.5 h70
  text "4" at 8231.51,8036.5 h70
  text "5" at 10730.5,8036.5 h70
  text "6" at 13235.5,8036.5 h70
  text "A" at -416.5,6893.5 h70
  text "A" at 14383.5,6893.5 h70
  text "B" at -416.5,4513.5 h70
  text "B" at 14383.5,4513.5 h70
  text "C" at -416.5,2138.5 h70
  text "C" at 14383.5,2138.5 h70
  text "PROJECT TITLE:" at 11343.5,277.5 h45
  text ".PRJ_Title" at 11393.5,144.17 h70
  text "DESIGNED FOR:" at 11343.5,-23.5 h45
  text ".PRJ_Customer" at 11393.5,-163.5 h70
  text "D" at -416.5,-231.5 h70
  text "D" at 14383.5,-231.5 h70
  text "FILE NAME:" at 11343.5,-323.5 h45
  text ".PCB_File_Name_No_Path" at 11393.5,-443.5 h70
  text "Texas Instruments (TI) and/or its licensors do not warrant the accuracy or completeness of this specification" at 6374,-605.34 h45
  text "ENGINEER:" at 11343.5,-613.5 h45
  text "LAYOUT BY:" at 12848.5,-613.5 h45
  text "or any information contained therein. TI and/or its licensors do not warrant that this design will meet" at 6329.01,-718 h45
  text ".PRJ_Engineer" at 11393.5,-768.49 h70
  text ".PCB_Layout" at 12899,-768.49 h70
  text "the specifications, will be suitable for your application or fit for any particular purpose, or will operate in" at 6329.01,-830.67 h45
  text ".Layer_Name" at 577,-858.49 h60
  text "ALTIUM DESIGNER VERSION:" at 12848.5,-923.5 h45
  text "an implementation. TI and/or its licensors do not warrant that the design is production worthy. You should" at 6329.01,-943.33 h45
  text "completely validate and test your design implementation to confirm the system functionality for your application." at 6374,-1056 h45
  text ".print_Scale" at 11393.5,-1056.83 h70
  text ".Application_BuildNumber" at 12899,-1056.83 h70
  text "1" at 739.84,-1263.5 h70
  text "2" at 3235.5,-1263.5 h70
  text "3" at 5724.84,-1263.5 h70
  text "4" at 8231.51,-1263.5 h70
  text "5" at 10730.5,-1263.5 h70
  text "6" at 13235.5,-1263.5 h70
M10 Fab Notes:
  drawing of 189 lines, arcs and shapes, not listed
  text "DESIGN INFORMATION" at 12382.02,6356.17 h60
  text "MIN. TRACK WIDTH:" at 11737.46,6224.05 h60
  text "8" at 12833.7,6224.05 h60
  text "MIL" at 12988.46,6224.05 h60
  text "MIN. CLEARANCE:" at 11737.46,6099.92 h60
  text "0.2" at 12773.7,6099.93 h60
  text "mm" at 12988.46,6099.92 h60
  text "MIN. VIA PAD SIZE:" at 11737.46,5975.8 h60
  text "24" at 12803.71,5975.8 h60
  text "MIL" at 12988.46,5975.8 h60
  text "0.05mm (2MIL)" at 12432.46,5845.9 h60
  text "MINIMUM ANNULAR RING" at 11408.23,5837.67 h60
  text "EXTERNAL" at 13140.46,5837.67 h60
  text "PER" at 11608.23,5727.55 h60
  text "IPC-D-275 CLASS 2 LEVEL C" at 11828.23,5727.54 h60
  text "MIL, HOLES" at 13316.46,5627.07 h60
  text "+/-" at 12924,5618.48 h60
  text "+/-" at 13778,5618.48 h60
  text "REGISTRATION TOLERANCES:" at 11408.23,5617.42 h60
  text "METAL" at 12608,5617.42 h60
  text "5" at 13184.2,5617.42 h60
  text "3" at 14017.2,5617.42 h60
  text "MIL" at 14133.46,5617.42 h60
  text "HOLE SIZE TOLERANCE (UNLESS OTHERWISE SPECIFIED):" at 11408.23,5519.1 h60
  text "+/-" at 13778,5516.23 h60
  text "3" at 14017.2,5515.17 h60
  text "MIL" at 14133.46,5515.17 h60
  text "MATERIAL:" at 11333.46,5377.52 h60
  text "FR-4 High Tg" at 12319.9,5249 h60
  text "X" at 12175.46,5241.01 h60
  text "FR-408" at 11754.46,5236.49 h60
  text "OTHER" at 13242.46,5236.49 h60
  text "62 MIL (1.6mm) +/-10%" at 12074.56,5093.46 h60
  text "X" at 11954.46,5091.01 h60
  text "THICKNESS:" at 11408.23,5085.24 h60
  text "OTHER" at 13359.46,5085.24 h60
  text "TOLERANCE:" at 11408.23,4946.92 h60
  text "X" at 12256.46,4946.92 h60
  text "ANSI IPC-6012 TYPE 3 CLASS 2" at 12434.48,4946.92 h60
  text "OTHER +/-" at 12434.46,4802.73 h60
  text "BOW & TWIST:" at 11408.23,4657.54 h60
  text "X" at 12256.46,4657.54 h60
  text "ANSI IPC-6012 TYPE 3 CLASS 2" at 12434.48,4657.54 h60
  text "OTHER +/-" at 12434.46,4510.85 h60
  text "DRILLING:" at 11333.46,4380.23 h60
  text "NC_DRILL FILES" at 13094.46,4275.04 h60
  text "REFERENCE:" at 11408.23,4271.1 h60
  text "X" at 12065.46,4271.01 h60
  text "AS SHOWN" at 12243.46,4271.1 h60
  text "X" at 12966.46,4271.1 h60
  text "OTHER" at 13392.46,4128.85 h60
  text "PTH COPPER THICKNESS:" at 11407.91,4125.32 h60
  text "X" at 12547.14,4125.32 h60
  text "20-30 um" at 12675.14,4125.32 h60
  text "BOARD FINISH:" at 11333.46,3977.73 h60
  text "SILKSCREEN:" at 11488.68,3867.6 h60
  text "X" at 12446.46,3867.6 h60
  text "TOP" at 12563.46,3867.6 h60
  text "X" at 12956.46,3867.6 h60
  text "BOTTOM" at 13074.46,3867.6 h60
  text "SILKSCREEN COLOR:" at 11488.68,3712.41 h60
  text "X" at 12445.46,3712.41 h60
  text "WHITE" at 12563.46,3712.41 h60
  text "OTHER" at 13074.46,3712.41 h60
  text "X" at 12576.46,3568.96 h60
  text "GREEN" at 12694.46,3568.96 h60
  text "OTHER" at 13312.46,3568.96 h60
  text "SOLDER RESIST COLOR:" at 11488.68,3562.1 h60
  text "X" at 12576.46,3414.71 h60
  text "MATTE" at 12694.46,3414.71 h60
  text "SEMI-GLOSS" at 13312,3414.07 h60
  text "IMMERSION GOLD (ENIG)" at 12394.46,3241.94 h60
  text "ENEPIG" at 13732,3234.72 h60
  text "SURFACE FINISH:" at 11333.46,3233.72 h60
  text "X" at 12216.46,3233.72 h60
  text "IMM. TIN/SILVER OR EQUIV" at 11663,3096.4 h60
  text "OTHER" at 13094.46,3092.47 h60
  text "ARRAY/PANEL:" at 11333.46,2937.09 h60
  text "CUT AND TRIM PER M1 BOARD OUTLINE" at 12394.46,2928.87 h60
  text "N.C. ROUTE" at 12394.46,2792.9 h60
  text "X" at 13082.46,2792.9 h60
  text "V. SCORE" at 13260.46,2792.9 h60
  text "CERTIFICATION:" at 11333.46,2663.77 h60
  text "MATERIALS AND WORKMANSHIP FOR ALL PCBS" at 12058.46,2663.77 h60
  text "TO MEET OR EXCEED THE REQUIREMENTS OF:" at 12058.46,2569.71 h60
  text "X" at 11695.97,2441.08 h60
  text "ANSI IPC-A-600F CLASS ->" at 11823.96,2441.08 h60
  text "X" at 13471.97,2441.08 h60
  text "2" at 13581.96,2441.08 h60
  text "1" at 13266.96,2439.58 h60
  text "3" at 13935.96,2439.58 h60
  text "X" at 12507.97,2293.39 h60
  text "RoHS" at 12635.96,2293.39 h60
  text "OTHER" at 13280.36,2293.39 h60
  text "PER ORDER" at 13677.42,2293.39 h60
  text "ALL BOARDS MUST MEET OR EXCEED UL94-V0 REQUIREMENTS." at 11361,2139.57 h60
  text "PCB MUST BEAR THE UL94V-0 UL REGISTERED MATERIAL ID NUMBER" at 11361,2023.5 h60
  text "ADDITIONAL REQUIREMENTS:" at 11333.46,1854.08 h60
  text "MICROSECTION:" at 11408.23,1746.95 h60
  text "YES" at 12313.96,1746.95 h60
  text "REQUIRED" at 13175.46,1602.62 h60
  text "BARE BOARD ELEC. TEST:" at 11408.23,1599.76 h60
  text "NONE" at 12713.96,1599.76 h60
  text "X" at 13057.46,1599.76 h60
  text "PER ORDER" at 13767.46,1599.76 h60
  text "XX MIL VIAS REQUIRE NON-CONDUCTIVE FILL AND PLANARIZE" at 11576.38,1394.82 h59
  text "XX MIL VIAS REQUIRE CONDUCTIVE FILL AND PLANARIZE" at 11584.38,1290.84 h60
  text "OUTER XX MIL TRACES REQUIRE 50 OHM SINGLE-ENDED IMPEDANCE" at 11583.39,1127.46 h58
  text "LAYER 2 & 3 (INNER LAYERS) XX MIL WIDE, XX MIL SPACE / TRACES REQUIRE 100 OHM DIFFERENTIAL IMPEDANCE" at 11575.39,891.74 h60
  text ".Layer_Name" at 577,-858.49 h60
M11 Gerber Information:
  lines w10: -292,-930.17 6308,-930.17 ; -292,-726.83 6310,-726.83 ; -292,-523.5 -292,-1133.5 3713,-1133.5 6310,-1133.5 6310,-523.5 -291.5,-523.5 -291.5,-1133.5 1284,-1133.5 ; 2173,-1133.5 2173,-523.5 ; 3440,-726.83 3440,-523.5 ; 4280,-726.83 4280,-523.5 ; 4902,-1140 4902,-937.17
  text "ALL ARTWORK VIEWED FROM TOP SIDE" at -228.5,-655.67 h60
  text "BOARD #:" at 2248,-655.67 h60
  text ".PRJ_Number" at 2793.5,-655.67 h60
  text "REV:" at 3638,-655.67 h60
  text ".PCB_Rev" at 3929.5,-655.67 h60
  text "SVN REV:" at 4476,-655.67 h60
  text ".VersionControl_RevNumber" at 4982,-655.67 h60
  text "LAYER NAME =" at -228.5,-858.49 h60
  text "TID #:" at 2248,-859 h60
  text ".TID" at 2793.5,-859 h60
  text "PLOT NAME =" at -228.5,-1064.34 h60
  text ".plot_File_Name" at 577,-1064.34 h60
  text "GENERATED    :" at 2250,-1064.34 h60
  text ".Print_Date" at 3119.5,-1064.34 h60
  text ".Print_Time" at 3848.5,-1064.34 h60
  text "TEXAS INSTRUMENTS" at 5113,-1064.34 h60
M12 Stackup:
  drawing of 295 lines, arcs and shapes, not listed
  text "Layer" at 9811.59,7649.94 h60
  text "Name" at 10221.51,7649.94 h60
  text "Material" at 11161.25,7649.94 h60
  text "Thickness" at 12021.02,7649.94 h60
  text "Constant" at 12670.85,7649.94 h60
  text "Board Layer Stack" at 13240.71,7649.94 h60
  text "1" at 9811.59,7529.94 h60
  text "Top Overlay" at 10221.51,7529.94 h60
  text "2" at 9811.59,7409.94 h60
  text "Top Solder" at 10221.51,7409.94 h60
  text "Solder Resist" at 11161.25,7409.94 h60
  text "0.40mil" at 12021.02,7409.94 h60
  text "3.5" at 12670.85,7409.94 h60
  text "3" at 9811.59,7289.94 h60
  text "Top Layer" at 10221.51,7289.94 h60
  text "Copper" at 11161.25,7289.94 h60
  text "2.80mil" at 12021.02,7289.94 h60
  text "4" at 9811.59,7169.94 h60
  text "Dielectric 1" at 10221.51,7169.94 h60
  text "FR-4" at 11161.25,7169.94 h60
  text "8.00mil" at 12021.02,7169.94 h60
  text "4.2" at 12670.85,7169.94 h60
  text "5" at 9811.59,7049.94 h60
  text "Signal Layer 1" at 10221.51,7049.94 h60
  text "Copper" at 11161.25,7049.94 h60
  text "1.40mil" at 12021.02,7049.94 h60
  text "6" at 9811.59,6929.94 h60
  text "Dielectric 2" at 10221.51,6929.94 h60
  text "FR-4" at 11161.25,6929.94 h60
  text "38.40mil" at 12021.02,6929.94 h60
  text "4.2" at 12670.85,6929.94 h60
  text "7" at 9811.59,6809.94 h60
  text "Signal Layer 2" at 10221.51,6809.94 h60
  text "Copper" at 11161.25,6809.94 h60
  text "1.40mil" at 12021.02,6809.94 h60
  text "8" at 9811.59,6689.94 h60
  text "Dielectric 3" at 10221.51,6689.94 h60
  text "FR-4" at 11161.25,6689.94 h60
  text "8.00mil" at 12021.02,6689.94 h60
  text "4.2" at 12670.85,6689.94 h60
  text "9" at 9811.59,6569.94 h60
  text "Bottom Layer" at 10221.51,6569.94 h60
  text "Copper" at 11161.25,6569.94 h60
  text "2.80mil" at 12021.02,6569.94 h60
  text "10" at 9811.59,6449.94 h60
  text "Bottom Solder" at 10221.51,6449.94 h60
  text "Solder Resist" at 11161.25,6449.94 h60
  text "0.40mil" at 12021.02,6449.94 h60
  text "3.5" at 12670.85,6449.94 h60
  text "11" at 9811.59,6329.94 h60
  text "Bottom Overlay" at 10221.51,6329.94 h60
  text ".Layer_Name" at 577,-858.49 h60
M13 Component Bodies Top:
  text ".Layer_Name" at 577,-858.49 h60
M14 Component Bodies Bottom:
  text ".Layer_Name" at 577,-858.49 h60
M15 Courtyards Top:
  text ".Layer_Name" at 577,-858.49 h60
M16 Courtyards Bottom:
  text ".Layer_Name" at 577,-858.49 h60
Drill Drawing:
  circle w10: c5363.72,3101.64 r27.63
  lines w10: 5336.09,2466.23 5349.9,2466.23 5349.9,2452.42 5377.53,2452.42 5377.53,2466.23 5391.34,2466.23 5391.34,2493.86 5377.53,2493.86 5377.53,2507.67 5349.9,2507.67 5349.9,2493.86 5336.09,2493.86 5336.09,2466.23 ; 5336.09,2631.99 5391.34,2631.99 5363.72,2576.74 5336.09,2631.99 ; 5336.09,2714.87 5349.9,2714.87 5363.72,2701.06 5377.53,2714.87 5391.34,2714.87 5377.53,2728.68 5391.34,2742.5 5377.53,2742.5 5363.72,2756.31 5349.9,2742.5 5336.09,2742.5 5349.9,2728.68 5336.09,2714.87 ; 5336.09,2825.38 5391.34,2825.38 5391.34,2880.63 5336.09,2880.63 5336.09,2825.38 ; 5336.09,2949.7 5363.72,2963.51 5391.34,2949.7 5377.53,2977.32 5391.34,3004.95 5363.72,2991.14 5336.09,3004.95 5349.9,2977.32 5336.09,2949.7 ; 5336.09,3225.96 5363.72,3198.34 5391.34,3225.96 5363.72,3253.59 5336.09,3225.96 ; 5336.09,3322.66 5336.09,3336.47 5349.9,3350.28 5336.09,3364.1 5336.09,3377.91 5349.9,3377.91 5363.72,3364.1 5377.53,3377.91 5391.34,3377.91 5391.34,3364.1 5377.53,3350.28 5391.34,3336.47 5391.34,3322.66 5377.53,3322.66 5363.72,3336.47 5349.9,3322.66 5336.09,3322.66
  lines w12: 5286,2415.12 8517.49,2415.12 ; 5286,3409.68 8517.49,3409.68 ; 5623.86,2290.8 5623.86,3534 ; 5955.86,2290.8 5955.86,3534 ; 6592.43,2290.8 6592.43,3534 ; 6851.57,2290.8 6851.57,3534 ; 7226.72,2290.8 7226.72,3534 ; 7951.05,2290.8 7951.05,3534 ; 5286,2290.8 8517.49,2290.8 8517.49,3534 5286,3534 5286,2290.8
  text "Symbol" at 5360.59,3446.98 h72
  text "Quantity" at 5661.16,3446.98 h72
  text "Finished Hole Size" at 5993.16,3446.98 h72
  text "Plated" at 6629.72,3446.98 h72
  text "Hole Type" at 6888.86,3446.98 h72
  text "Drill Layer Pair" at 7264.02,3446.98 h72
  text "Hole Tolerance" at 7988.35,3446.98 h72
  text "9" at 5661.16,3322.66 h60
  text "7.87mil (0.200mm)" at 5993.16,3322.66 h60
  text "PTH" at 6629.72,3322.66 h60
  text "Round" at 6888.86,3322.66 h60
  text "Top Layer - Bottom Layer" at 7264.02,3322.66 h60
  text "570" at 5661.16,3198.34 h60
  text "12.00mil (0.305mm)" at 5993.16,3198.34 h60
  text "PTH" at 6629.72,3198.34 h60
  text "Round" at 6888.86,3198.34 h60
  text "Top Layer - Bottom Layer" at 7264.02,3198.34 h60
  text "4" at 5661.16,3074.02 h60
  text "25.59mil (0.650mm)" at 5993.16,3074.02 h60
  text "PTH" at 6629.72,3074.02 h60
  text "Round" at 6888.86,3074.02 h60
  text "Top Layer - Bottom Layer" at 7264.02,3074.02 h60
  text "9" at 5661.16,2949.7 h60
  text "33.47mil (0.850mm)" at 5993.16,2949.7 h60
  text "PTH" at 6629.72,2949.7 h60
  text "Round" at 6888.86,2949.7 h60
  text "Top Layer - Bottom Layer" at 7264.02,2949.7 h60
  text "21" at 5661.16,2825.38 h60
  text "40.00mil (1.016mm)" at 5993.16,2825.38 h60
  text "PTH" at 6629.72,2825.38 h60
  text "Round" at 6888.86,2825.38 h60
  text "Top Layer - Bottom Layer" at 7264.02,2825.38 h60
  text "6" at 5661.16,2701.06 h60
  text "45.28mil (1.150mm)" at 5993.16,2701.06 h60
  text "PTH" at 6629.72,2701.06 h60
  text "Round" at 6888.86,2701.06 h60
  text "Top Layer - Bottom Layer" at 7264.02,2701.06 h60
  text "6" at 5661.16,2576.74 h60
  text "51.18mil (1.300mm)" at 5993.16,2576.74 h60
  text "PTH" at 6629.72,2576.74 h60
  text "Round" at 6888.86,2576.74 h60
  text "Top Layer - Bottom Layer" at 7264.02,2576.74 h60
  text "+/-3.94mil" at 7988.35,2576.74 h60
  text "2" at 5661.16,2452.42 h60
  text "51.18mil (1.300mm)" at 5993.16,2452.42 h60
  text "PTH" at 6629.72,2452.42 h60
  text "Round" at 6888.86,2452.42 h60
  text "Top Layer - Bottom Layer" at 7264.02,2452.42 h60
  text "627 Total" at 5661.16,2328.1 h60
  text ".Layer_Name" at 577,-858.49 h60
Mechanical 17:
  text ".Layer_Name" at 577,-858.49 h60
Mechanical 18:
  text ".Layer_Name" at 577,-858.49 h60
Mechanical 19:
  text ".Layer_Name" at 577,-858.49 h60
